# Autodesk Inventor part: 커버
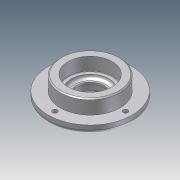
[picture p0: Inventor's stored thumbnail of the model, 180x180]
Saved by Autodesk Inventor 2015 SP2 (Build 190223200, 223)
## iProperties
Company: 한국ATC센터
Created: 2014-10
Part Number: 커버
Document SubType Name: Modeling
Designer: KYOUNG IL JANG
Density: 7.85 g/cm^3
Mass: 44.7286 g
Surface Area: 161.165 cm^2
Volume: 44.7286 cm^3
Material: 강철
Appearance: 강철
Author: KYOUNG IL JANG
Revision Number: 1
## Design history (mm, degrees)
sketch "스케치1"
  geometry: C1 r 38 at (0, 0); 1 further point
  constraints: 1 centre point, 1 coincident
  dimensions: "d0" = 76 diameter of C1
extrude "돌출1" new body sketch "스케치1" distance "d1" = 7; taper "d2" = 0 deg
sketch "스케치2"
  geometry: C1 r 27 at (0, 0); 1 further point
  constraints: 1 centre point, 1 coincident
  dimensions: "d3" = 54 diameter of C1
extrude "돌출2" join sketch "스케치2" distance "d4" = 13; taper "d5" = 0 deg
sketch "스케치3"
  geometry: C1 r 20 at (0, 0); 1 further point
  constraints: 1 centre point, 1 coincident
  dimensions: "d6" = 40 diameter of C1
extrude "돌출3" join sketch "스케치3" distance "d7" = 5; taper "d8" = 0 deg
hole "구멍1" diameter "d11" = 25; stored, may be unused: countersink angle "d15" = 90 deg, drill point angle "d17" = 118 deg; dims "d9" = 10, "d10" = 10, "d12" = 6, "d13" = 32, "d14" = 8.3, "d16" = 8
hole "구멍2" diameter "d20" = 34; stored, may be unused: countersink angle "d24" = 90 deg, drill point angle "d26" = 0 deg; dims "d18" = 10, "d19" = 10, "d21" = 6, "d22" = 40, "d23" = 12, "d25" = 3
fillet "모깎기2" dims "d34" = 3
fillet "모깎기1" dims "d27" = 0.3
chamfer "모따기1" distance "d28" = 1; stored, may be unused: second distance "d29" = 2, angle "d30" = 45 deg
chamfer "모따기2" distance "d31" = 1.2; stored, may be unused: second distance "d32" = 2, angle "d33" = 30 deg
sketch "스케치4" dims "d35" = 64
  geometry: 3 further points
  constraints: 2 horizontal alignment, 1 coincident, 2 other
hole "구멍3" sketch "스케치4" at (32, 0) diameter "d36" = 4.5; stored, may be unused: countersink angle "d40" = 90 deg, drill point angle "d42" = 118 deg; dims "d37" = 6, "d38" = 8, "d39" = 4.4, "d41" = 13
node "솔리드1"
pattern_circular "원형 패턴1" dims angle "d44" = 360 deg
